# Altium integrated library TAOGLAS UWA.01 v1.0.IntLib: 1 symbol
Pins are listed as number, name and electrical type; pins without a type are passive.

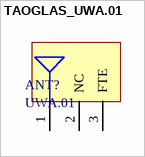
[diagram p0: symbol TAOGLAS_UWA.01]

## TAOGLAS_UWA.01
designator ANT?, comment UWA.01
6-9GHz UWB Ceramic Substrate Antenna; ComponentLibStatus: Created; MFG: Taoglas; Temp_High: +105C; Temp_Low: -40C
footprint TAOGLAS_UWA.01 (6-9GHz UWB Ceramic Substrate Antenna)
pins: 1 RF FEED, 2 NC, 3 FTE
